// Mitsubishi GX Works2 project: Flowsort_FB_V3.1_20240104   PLC: Q13UDV

// task test123 (event TRUE, interval 0, priority 31): Flowsort_Test

FUNCTION_BLOCK Flowsort
VAR_INPUT
  bEnable : BOOL;  (* Enable the module roller MDR start rolling and disc function Enable *)
  bHoming_Trigger : BOOL;  (* The Homing cycle is activated by a positive edge at this input *)
  bRoller_Execute : BOOL;  (* Start Rollers *)
  bSortPos_Execute : BOOL;  (* Execute go to selected position *)
END_VAR
VAR_OUTPUT
  bStat_CommOK : BOOL;  (* State Homing of Disk executed Correctly *)
  bStat_HomingOK : BOOL;  (* State Communication to Module OK *)
  BStat_InPositionDisc : BOOL;  (* State Disk is in Position *)
  bStat_Ready_Disc : BOOL;  (* State Disk Ready for Positioning *)
  bStat_Ready_Roller : BOOL;  (* State Roller Ready *)
END_VAR
VAR_INPUT
  bMDR_Heartbeat : BOOL;  (* Heartbeat signal from Conveylinxmodule *)
  sMDR_DiscDiagnostic : WORD;  (* Disc MDR diagnostics from Conveylinxmodule *)
  sMDR_RollerDiagnostic : WORD;  (* Roller MDR diagnostics from Conveylinxmodule *)
  iMDR_DistanceDisc : INT;  (* Actual Position Disc Motor from Conveylinxmodule *)
  wMDRStatusDisk : WORD;  (* Servo State Feedback Disc from Conveylinxmodule *)
  wMDRStatusRoller : WORD;  (* Servo State Feedback Rollers from Conveylinxmodule *)
END_VAR
VAR_OUTPUT
  iMDR_Speed_Disc : INT;  (* Speed to Conveylinxmodule *)
  iMDR_BrakeMode_Disc : INT;  (* Brakemode to Conveylinxmodule *)
  iMDR_Acc_Disc : INT;  (* Acceleration to Conveylinxmodule *)
  iMDR_Dec_Disc : INT;  (* Decceleration to Conveylinxmodule *)
  iMDR_Speed_Roller : INT;  (* Speed to Conveylinxmodule *)
  iMDR_BrakeMode_Roller : INT;  (* Brakemode to Conveylinxmodule *)
  iMDR_Acc_Roller : INT;  (* Acceleration to Conveylinxmodule *)
  iMDR_Dec_Roller : INT;  (* Decceleration to Conveylinxmodule *)
  iMDR_ControlMotor_Disc : WORD;  (* MDR Crtl to Conveylinxmodule *)
  iMDR_ServoCTRL_Disc : WORD;  (* Servo controll command to Conveylinxmodule *)
  iMDR_ControlDistance_Disk : INT;  (* Requested position to Conveylinxmodule *)
  iMDR_ControlMotor_Roller : WORD;  (* MDR Crtl to Conveylinxmodule *)
END_VAR
VAR_INPUT
  iGearRatio_Disk : INT;  (* Gear ratio of the PGD Motor pulse rotation disk *)
  iGearRatio_Roller : INT;  (* Gear ratio of the PGD Motor Pulse Roller *)
  iHomePositionOffset : INT;  (* Offset Home Sensor to zero position *)
  iMechanicRatio_Disk : INT;  (* Mechanical ratio of the of the system rotation disk *)
  iMechanicRatio_Roller : INT;  (* Mechanical ratio of the system roller *)
  iRollerSpeed : INT;  (* Rotational speed rollers 0 - 100% *)
  iRotationSpeed : INT;  (* Rotational speed sort discs 0 - 100% *)
  iSortPos_LEFT : INT;  (* Sorting Position Left *)
  iSortPos_Location : INT;  (* Disc position to sort (0 = MID, 1= LEFT, 2= RIGHT) *)
  iSortPos_MID : INT;  (* Sorting Position Middle *)
  iSortPos_RIGHT : INT;  (* Sorting Position Right *)
END_VAR
VAR
  ActSpeedDisc : INT;
  ActSpeedRoll : INT;
END_VAR
VAR_INPUT
  bMDR_Homing_Sensor_Disk : BOOL;  (* Home sensor in the SLD/DLD module *)
END_VAR
VAR_OUTPUT
  wSTAT_DiagnosticDisc : WORD;  (* Diagnostic Status of Disc motor *)
  wSTAT_DiagnosticRoller : WORD;  (* Diagnostic Status of Roller motor *)
END_VAR
VAR
  CorrectionPulsePos : DINT;  (* Disk correction in pulse *)
  Heartbeat_Lastscan : BOOL;
  Heartbeat_Timer : TON;
  HomeExecutedCorrect : BOOL;  (* Last home execute OK *)
  HomeRunning : BOOL;  (* Homing sequente is Running *)
  Homing_Steps : INT;  (* Case program steps *)
  OSFI_01 : F_TRIG;
  OSRI_01 : R_TRIG;
  OSRI_02 : R_TRIG;
  RemainingDistance : DINT;
  SortPulsePos_LEFT : DINT;  (* Sort positon in Pulse left *)
  SortPulsePos_MID : DINT;  (* Sort positon in Pulse Midle *)
  SortPulsePos_RIGHT : DINT;  (* Sort positon in Pulse Right *)
  Timeout_Timer_Homing : TON;
  WaitForReset : TON;
  WaitForReturn : TON;
  MaxPulseDisc : INT;  (* Max. MDR Pulse speed *)
  MaxPulseRoller : INT;  (* Max. MDR Pulse speed *)
  MinPulseDisc : INT;  (* Min. MDR Pulse speed *)
  MinPulseRoller : INT;  (* Min. MDR Pulse speed *)
  ServoCommandExecuted : BOOL;  (* Feedback Servo Command is executed by Motor *)
  TempTestBit : INT;
END_VAR
(* Flowsort bv 24V Diverter Function Block
Release 04/01/2024 V3.1 *)


(* Region MotorType_Disk *)

(* Value conversion OF motor type FOR turning disk

//Motor ratio puls conversion
//	Motor ratio 9			min 640			max 6450
//	Motor ratio 11			min 520			max 5280
//	Motor ratio 15			min 380			max 3870
//	Motor ratio 18			min 310			max 3170
//  Motor ratio 33			min 174			max 1760 *)

CASE iGearRatio_Disk OF

	9:		MinPulseDisc		:=	640;
			MaxPulseDisc		:=	6450;

	11:		MinPulseDisc		:=	520;
			MaxPulseDisc		:=	5280;

	15:		MinPulseDisc		:=	380;
			MaxPulseDisc		:=	3870;

	18:		MinPulseDisc		:=	310;
			MaxPulseDisc		:=	3170;
			
	33: 	MinPulseDisc		:= 	174;
			MaxPulseDisc		:=	1760;

END_CASE;

(*Scale function FOR Disk speed in relation with input setpoint speed 0%-100% *)

IF NOT HomeRunning AND HomeExecutedCorrect THEN
	ActSpeedDisc := (iRotationSpeed*((MaxPulseDisc-MinPulseDisc)/100)+MinPulseDisc);
	IF ActSpeedDisc>MaxPulseDisc THEN
		ActSpeedDisc:=MaxPulseDisc;
	END_IF;
	IF ActSpeedDisc < MinPulseDisc THEN
		ActSpeedDisc := MinPulseDisc;
	END_IF;
END_IF;
	

(* Region MotorType_Roller *)

(* Value conversion OF motor type FOR blue rollers

//Motor ratio puls conversion
//	Motor ratio 5			min 840			max 8400
//	Motor ratio 9			min 640			max 6450
//	Motor ratio 11			min 520			max 5280
//	Motor ratio 15			min 380			max 3870
//	Motor ratio 18			min 310			max 3170  *)

CASE iGearRatio_Roller OF

	5:		MinPulseRoller		:=840;
			MaxPulseRoller		:=8400;

	9:		MinPulseRoller		:=640;
			MaxPulseRoller		:=6450;

	11:		MinPulseRoller		:=520;
			MaxPulseRoller		:=	5280;

	15:		MinPulseRoller		:=380;
			MaxPulseRoller		:=	3870;

	18:		MinPulseRoller		:=	310;
			MaxPulseRoller		:=	3170;

END_CASE;

(*Scale function FOR Disk speed in relation with input setpoint speed 0%-100% *)

	ActSpeedRoll:= (iRollerSpeed* ((MaxPulseRoller- MinPulseRoller)/100)+ MinPulseRoller);
	IF ActSpeedRoll > MaxPulseRoller THEN
		ActSpeedRoll:= MaxPulseRoller;
	END_IF;
	IF ActSpeedRoll< MinPulseRoller THEN
		ActSpeedRoll:= MinPulseRoller;
	END_IF;
(* Region Set_MDR_Parameters *)

	iMDR_BrakeMode_Disc		:= 3;					(*Set MDR in servo brake mode. *)
	iMDR_BrakeMode_Roller		:= 1; 				(* Set MDR in standard brake mode. *)
	iMDR_Acc_Roller						:= 500;			(* Acceleration roller speed in pulse/min	*)
	iMDR_Dec_Roller					:= 500;			(* Decceleration roller speed in pulse/min	*)

(* Region CorrectionToPulse *)

CorrectionPulsePos	:= INT_TO_DINT(((iHomePositionOffset *30 * iGearRatio_Disk * iMechanicRatio_Disk) /360));
SortPulsePos_MID	:= INT_TO_DINT(((iSortPos_MID *30 * iGearRatio_Disk * iMechanicRatio_Disk) /360));
SortPulsePos_LEFT	:= INT_TO_DINT(((iSortPos_LEFT *30 * iGearRatio_Disk * iMechanicRatio_Disk) /360));
SortPulsePos_RIGHT	:= INT_TO_DINT(((iSortPos_RIGHT *30 * iGearRatio_Disk * iMechanicRatio_Disk) /360));

(* Region Enable *)

    IF bEnable = 0 THEN                           			
		HomeRunning 								:= FALSE;					(*Homing end*)
		Homing_Steps								:= 0;								(* Rst steps*)
		BRST_M (TRUE,1,iMDR_ServoCTRL_Disc)	;		(*Servo Cmd to go to a position*)
		BRST_M (TRUE,0,iMDR_ServoCTRL_Disc);		(* Servo Cmd to Rst the position to 0*)
		BRST_M (TRUE,0,iMDR_ControlMotor_Disc);		(*Motor Cmd to run*)
		BRST_M (TRUE,6,iMDR_ControlMotor_Disc);		(*Motor Cmd to run*)
		BRST_M (TRUE,0,iMDR_ControlMotor_Roller);	(* Motor Cmd to run*)
   END_IF;

(* Region Homing Module *)

(*Rising edge OF the homing trigger start the homing sequentie.  *)

WaitForReset(IN := (Homing_Steps = 3), PT := T#500ms);
WaitForReturn(IN :=  (Homing_Steps = 4), PT := T#500ms);

TempTestBit := WORD_TO_INT(wMDRStatusDisk);
ServoCommandExecuted := (GET_BIT_OF_INT(TempTestBit, 0)) ;

OSRI_01(_CLK := bHoming_Trigger);

IF (OSRI_01.Q AND bEnable) OR HomeRunning THEN

			iMDR_Acc_Disc			:= 10000;					(* Set low speed FOR correct homing*)
			iMDR_Dec_Disc  			:= 30;							(* Set low speed FOR correct homing*)
			iMDR_Speed_Disc		:= MinPulseDisc;	(*Set low speed for correct homing*)

	CASE Homing_Steps OF
	0:	(*Init step *)
			HomeRunning 											:= 1;			(* Homing execute*)
			HomeExecutedCorrect							:= 0;			(* IF homing is done correct THEN ok*)
			BRST_M (TRUE,1,iMDR_ServoCTRL_Disc)	;		(*Servo Cmd to go to a position*)
			BRST_M (TRUE,0,iMDR_ServoCTRL_Disc);		(* Servo Cmd to Rst the position to 0*)
			BRST_M (TRUE,0,iMDR_ControlMotor_Disc);		(*Motor Cmd to stop*)
			Homing_Steps											:= 1;

	1:		(* Turn disc low speed till home sensor*)
			IF ServoCommandExecuted THEN                               (* All servo command are done*)
                    IF NOT bMDR_Homing_Sensor_Disk THEN
                        BSET_M (TRUE,0,iMDR_ControlMotor_Disc);		(*Motor Cmd to run*)
                        BRST_M (TRUE,8,iMDR_ControlMotor_Disc);		(*  Motor Cmd direction*)
                    ELSE
                        BSET_M (TRUE,6,iMDR_ControlMotor_Disc);		(*Motor Cmd to run*)                               
                        BRST_M (TRUE,8,iMDR_ControlMotor_Disc);		(*  Motor Cmd direction*)                          
                        Homing_Steps										:= 2;					(* Go next step*)                    
                        END_IF;
            END_IF;
	

	2:(*  When falling Edge Motor Running Reset postion to zero*)
		OSFI_01(_CLK:= (GET_BIT_OF_INT(TempTestBit, 1)));
		
		IF OSFI_01.Q THEN												(*Faling edge OF the home sensor stop the turning*)
			BRST_M (TRUE,6,iMDR_ControlMotor_Disc);		(*Motor Cmd to run*)
			Homing_Steps								:= 3;				(*Go next step*)
		END_IF;

	3:	(*Wait for Reset position Execution Correction of the disk *)
 		IF WaitForReset.Q THEN	
 			BSET_M (TRUE,0,iMDR_ServoCTRL_Disc);		(* Servo Cmd to Rst the position to 0*)
		END_IF;	
		IF iMDR_DistanceDisc >= -1 AND iMDR_DistanceDisc <= 1 AND WaitForReset.Q THEN 	(* feedback servo rst execute*)
			BRST_M (TRUE,0,iMDR_ServoCTRL_Disc);		(* Servo Cmd to Rst the position to 0*)
			Homing_Steps								:= 4;			(*Go next step*)
		END_IF;

	4:(* Go to Zero Position *)
		IF WaitForReturn.Q THEN
			iMDR_ControlDistance_Disk	:= DINT_TO_INT(CorrectionPulsePos);	(* Load correction position angle to the set position*)
			BSET_M (TRUE,1,iMDR_ServoCTRL_Disc)	;		(*Servo Cmd to go to a position*)
			BRST_M (TRUE,0,iMDR_ServoCTRL_Disc);		(* Servo Cmd to Rst the position to 0*)
			Homing_Steps								:= 5;			(*Go next step*)
		END_IF;
	
	5:	(* RST position to zero when deviation is done *)
	 	IF ServoCommandExecuted THEN			(* feedback last servo command is execute*)
			BRST_M (TRUE,1,iMDR_ServoCTRL_Disc);		(*Servo Cmd to go to a position*)
 			BSET_M (TRUE,0,iMDR_ServoCTRL_Disc);		(* Servo Cmd to Rst the position to 0*)
			Homing_Steps								:= 6;			(* Go next step*)
		END_IF;

	6:		(* When Position is Zero Homing complete *)
		IF iMDR_DistanceDisc >= -1 AND iMDR_DistanceDisc <= 1 THEN	(* feedback servo rst execute*)
			BRST_M (TRUE,1,iMDR_ServoCTRL_Disc);		(*Servo Cmd to go to a position*)
 			BRST_M (TRUE,0,iMDR_ServoCTRL_Disc);		(* Servo Cmd to Rst the position to 0*)
			Homing_Steps								:= 50;			(* Go next step *)
		END_IF;

	50 : 	HomeExecutedCorrect				:= 1;			(* Last homing execute correct*)
			HomeRunning 								:= 0;			(* Homing end*)
			Homing_Steps								:= 0;			(* Rst steps*)
			BRST_M (TRUE,1,iMDR_ServoCTRL_Disc);		(*Servo Cmd to go to a position*)
 			BRST_M (TRUE,0,iMDR_ServoCTRL_Disc);		(* Servo Cmd to Rst the position to 0*)
 			BRST_M (TRUE,6,iMDR_ControlMotor_Disc);		(*Motor Cmd to stop*)
			BRST_M (TRUE,0,iMDR_ControlMotor_Disc);		(*Motor Cmd to stop*)
	99:		HomeExecutedCorrect				:= 0;			(*Last homing execute correct*)
			HomeRunning 								:= 0;			(*Homing end*)
			Homing_Steps								:= 0;			(* Rst steps*)
			BRST_M (TRUE,1,iMDR_ServoCTRL_Disc);		(*Servo Cmd to go to a position*)
 			BRST_M (TRUE,0,iMDR_ServoCTRL_Disc);		(* Servo Cmd to Rst the position to 0*)
			BRST_M (TRUE,0,iMDR_ControlMotor_Disc);		(*Motor Cmd to stop*)
			BRST_M (TRUE,6,iMDR_ControlMotor_Disc);		(*Motor Cmd to stop*)

	END_CASE;
END_IF;
Timeout_Timer_Homing(IN := HomeRunning, PT := T#20s);

IF Timeout_Timer_Homing.Q THEN
	HomeExecutedCorrect				:= 0;			(*Last homing execute correct*)
	HomeRunning 								:= 0;			(* Homing end*)
	Homing_Steps								:= 0;			(*Rst steps*)
			BRST_M (TRUE,1,iMDR_ServoCTRL_Disc);		(*Servo Cmd to go to a position*)
 			BRST_M (TRUE,0,iMDR_ServoCTRL_Disc);		(* Servo Cmd to Rst the position to 0*)
			BRST_M (TRUE,0,iMDR_ControlMotor_Disc);		(*Motor Cmd to stop*)
			BRST_M (TRUE,6,iMDR_ControlMotor_Disc);		(*Motor Cmd to stop*)
END_IF;

(* Region Sorting *)

	OSRI_02(_CLK:= bSortPos_Execute);
	IF (OSRI_02.Q AND HomeExecutedCorrect AND bEnable) THEN
		IF		iSortPos_Location	= 2	THEN
			iMDR_ControlDistance_Disk	:= DINT_TO_INT(SortPulsePos_RIGHT);	(*  Load correction position angle to the set position*)
		ELSIF	iSortPos_Location	= 1	THEN
			iMDR_ControlDistance_Disk	:= DINT_TO_INT(SortPulsePos_LEFT);	(* Load correction position angle to the set position*)
		ELSE
			iMDR_ControlDistance_Disk	:= DINT_TO_INT(SortPulsePos_MID);	(* Load correction position angle to the set position*)
		END_IF;
			RemainingDistance := INT_TO_DINT(ABS(iMDR_ControlDistance_Disk) + ABS(iMDR_ControlDistance_Disk) * 360 / 30 / iGearRatio_Disk / iMechanicRatio_Disk);
			iMDR_Speed_Disc 							:= ActSpeedDisc;
			BSET_M (TRUE,1,iMDR_ServoCTRL_Disc);		(*Servo Cmd to go to a position*)
			BStat_InPositionDisc						:= 0;
	END_IF;
	
	IF ServoCommandExecuted THEN									(* feedback last servo command is execute *)
			BRST_M (TRUE,1,iMDR_ServoCTRL_Disc);		(*Servo Cmd to go to a position*)
			BStat_InPositionDisc						:= 1;					(* command to execute to servo position *)
	END_IF;

	IF (HomeExecutedCorrect) THEN                               	(*FOR smoother positioning how smaller the distance the higher acc/dec is used*)
    	IF (RemainingDistance > 100) THEN                       	(*When angle higher than 100 degrees use higher Acc & Dec*)
    		iMDR_Acc_Disc			:= 120;									(*  Acceleration disk speed in pulse/min*)
    		iMDR_Dec_Disc  			:= 120;							 		(* Decceleration disk speed in pulse/min*)
    	ELSIF (RemainingDistance > 60) THEN
       	 	iMDR_Acc_Disc			:= 250;               						(*  Acceleration disk speed in pulse/min*)
        	iMDR_Dec_Disc			:= 250;              						(* Decceleration disk speed in pulse/min*)
    	ELSIF (RemainingDistance > 30) THEN
        	iMDR_Acc_Disc 			:= 350;                    				 (* Acceleration disk speed in pulse/min*)
        	iMDR_Dec_Disc			:= 350;									(*Decceleration disk speed in pulse/min*)
    	ELSE
        	iMDR_Acc_Disc := 500;                   							 (* Acceleration disk speed in pulse/min*)
        	iMDR_Dec_Disc := 500;											(*Decceleration disk speed in pulse/min*)
    	END_IF;
	END_IF;

(* Region Rollers *)
	BSET_M ((bRoller_Execute AND bEnable),0,iMDR_ControlMotor_Roller);	(* Motor Cmd to run*)
   iMDR_Speed_Roller := ActSpeedRoll;
   
   (* Region Communication *)
   Heartbeat_Timer(IN:= (Heartbeat_Lastscan AND bMDR_Heartbeat) OR ( NOT Heartbeat_Lastscan AND NOT bMDR_Heartbeat), PT:=t#5s);
    Heartbeat_Lastscan := bMDR_Heartbeat;              (*Heartbeat toggles every 2 seconds, when 5 seconds no toggle communication failure*)
    bStat_CommOK := NOT Heartbeat_Timer.Q;
	
   (* Region Status *)

    bStat_HomingOK := HomeExecutedCorrect;                   (* Homing executed OK*)
    wSTAT_DiagnosticDisc := sMDR_DiscDiagnostic;
    TempTestBit := WORD_TO_INT( sMDR_DiscDiagnostic);
    
    IF (NOT (GET_BIT_OF_INT(TempTestBit, 7))(*LowVoltage*) AND NOT 
		(GET_BIT_OF_INT(TempTestBit, 14)) (*MDRBadHall*) AND NOT (GET_BIT_OF_INT(TempTestBit, 11)) (*MDRNotConnected*) AND NOT
		(GET_BIT_OF_INT(TempTestBit, 13)) (*Stalled*) AND NOT (GET_BIT_OF_INT(TempTestBit, 8))  (*Overheat*) AND NOT
		(GET_BIT_OF_INT(TempTestBit, 12))  (*Overload*) AND NOT (GET_BIT_OF_INT(TempTestBit, 2))(*Overvoltage*)   AND NOT
		(GET_BIT_OF_INT(TempTestBit, 10))  (*ShortCircuit*) AND
		bStat_CommOK AND bStat_HomingOK) THEN
        bStat_Ready_Disc := 1;                             (*When no Diagnostic failure bit is active, communication is OK AND Homing is OK Disk is ready FOR positioning*)
    ELSE
        bStat_Ready_Disc := 0;
    END_IF;
    
	wSTAT_DiagnosticRoller := sMDR_RollerDiagnostic;
	TempTestBit := WORD_TO_INT( sMDR_RollerDiagnostic);
    
    IF (NOT (GET_BIT_OF_INT(TempTestBit, 7))(*LowVoltage*) AND NOT 
		(GET_BIT_OF_INT(TempTestBit, 14)) (*MDRBadHall*) AND NOT (GET_BIT_OF_INT(TempTestBit, 11)) (*MDRNotConnected*) AND NOT
		(GET_BIT_OF_INT(TempTestBit, 13)) (*Stalled*) AND NOT (GET_BIT_OF_INT(TempTestBit, 8))  (*Overheat*) AND NOT
		(GET_BIT_OF_INT(TempTestBit, 12))  (*Overload*) AND NOT (GET_BIT_OF_INT(TempTestBit, 2))(*Overvoltage*)   AND NOT
		(GET_BIT_OF_INT(TempTestBit, 10))  (*ShortCircuit*) AND
		bStat_CommOK) THEN
        bStat_Ready_Roller := 1;                             (* When no Diagnostic failure bit is active and communication is OK Roller is ready to Start*)
    ELSE
        bStat_Ready_Roller := 0;
    END_IF;
END_FUNCTION_BLOCK

PROGRAM Flowsort_Test
VAR
  Flowsort_1 : Flowsort;
END_VAR
(* structured ladder/FBD written out as ST: instructions are called as NAME(EN, inputs, outputs); _pN, _eN, _tN stand for wires *)
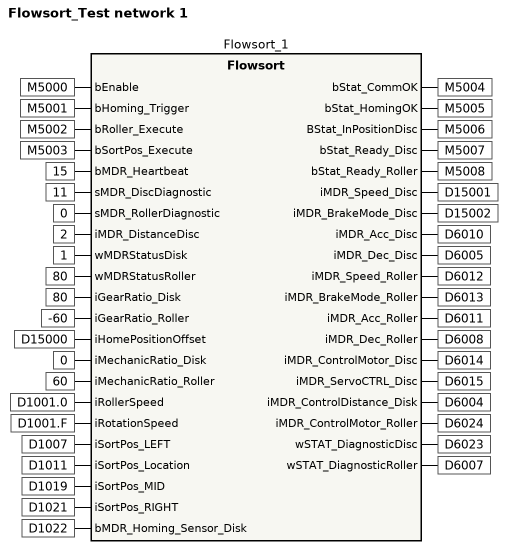
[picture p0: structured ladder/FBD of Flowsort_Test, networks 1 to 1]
(* network 1 *)
Flowsort_1(bEnable := M5000, bHoming_Trigger := M5001, bRoller_Execute := M5002, bSortPos_Execute := M5003, bMDR_Heartbeat := 15, sMDR_DiscDiagnostic := 11, sMDR_RollerDiagnostic := 0, iMDR_DistanceDisc := 2, wMDRStatusDisk := 1, wMDRStatusRoller := 80, iGearRatio_Disk := 80, iGearRatio_Roller := -60, iHomePositionOffset := D15000, iMechanicRatio_Disk := 0, iMechanicRatio_Roller := 60, iRollerSpeed := D1001.0, iRotationSpeed := D1001.F, iSortPos_LEFT := D1007, iSortPos_Location := D1011, iSortPos_MID := D1019, iSortPos_RIGHT := D1021, bMDR_Homing_Sensor_Disk := D1022, bStat_CommOK => M5004, bStat_HomingOK => M5005, BStat_InPositionDisc => M5006, bStat_Ready_Disc => M5007, bStat_Ready_Roller => M5008, iMDR_Speed_Disc => D15001, iMDR_BrakeMode_Disc => D15002, iMDR_Acc_Disc => D6010, iMDR_Dec_Disc => D6005, iMDR_Speed_Roller => D6012, iMDR_BrakeMode_Roller => D6013, iMDR_Acc_Roller => D6011, iMDR_Dec_Roller => D6008, iMDR_ControlMotor_Disc => D6014, iMDR_ServoCTRL_Disc => D6015, iMDR_ControlDistance_Disk => D6004, iMDR_ControlMotor_Roller => D6024, wSTAT_DiagnosticDisc => D6023, wSTAT_DiagnosticRoller => D6007);
END_PROGRAM

// device comments not shown above
M5000  ; Enable the module roller MDR sta
M5001  ; The Homing cycle is activated by
M5002  ; Start Rollers
M5003  ; Execute go to selected position
M5004  ; State Homing of Disk executed Co
M5005  ; State Communication to Module OK
M5006  ; State Disk is in Position
M5007  ; State Disk Ready for Positioning
M5008  ; State Roller Ready
D1007  ; [Left    Motor   Status]
D1011  ; [Left    Motor   Status]
D1019  ; [Left   Motor   Servo   Pos.]
D1021  ; [Left   Motor   Servo   Status.]
D1022  ; [Right  Motor   Servo   Status.]
D6004  ; [Left   Motor   Run]
D6005  ; [L_BK]  1;Stndrd2:Free, 3:Servo
D6007  ; [Right  Motor   Run]
D6008  ; [R_BK]  1;Stndrd2:Free, 3:Servo
D6010  ; [L_MotorSPD]    RPMx10
D6011  ; [R_MotorSPD]    mm/s
D6012  ; [L_MotorACC]    pulse  (30~10000
D6013  ; [L_MotorDEC]    pulse  (0~10000)
D6014  ; [R_MotorACC]    mm     (30~10000
D6015  ; [R_MotorDEC]    mm     (0~10000)
D6023  ; [L_ServoPositionCMD]-32767~32767
D6024  ; [L_Servo CMD]   SET"0"  / RUN
D15000  ; Sort Pos 0 = Mid 1=Left 2=Right
D15001  ; Diagnostic Status Disc
D15002  ; Diagnostic Status Roller
D1001.0  ; Left Sens Port - Aux (M8 Pin2)
D1001.F  ; Heartbeat       2Sec On 2Sec Off
